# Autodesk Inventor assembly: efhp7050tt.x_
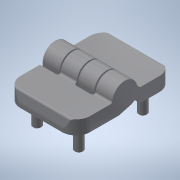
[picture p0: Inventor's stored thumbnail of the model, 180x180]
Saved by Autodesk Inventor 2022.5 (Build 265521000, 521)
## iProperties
Part Number: efhp7050tt.x_
Material: 一般
Document SubType Name: Assembly
Designer: ImaoCorp
Sending System: SOLIDWORKS 2017-2017317
MC: AMD64
MC_MODEL: Intel64 Family 6 Model 60 Stepping 3, GenuineIntel
OS: Windows_NT
FRU: Parasolid Version 29.0, build 201,  4-17-2017
FORMAT: text
GUISE: transmit
KEY: efhp7050tt
FILE: efhp7050tt.x_t
DATE: Mon May 13 14:22:51 2019
Author: ImaoCorp
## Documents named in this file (4)
- X:\14_SW2022-Inv2022\00_全2023-1023新製品(TCC)まで\e\efhp7050tt\EFHP7050TT.iam
- X:\14_SW2022-Inv2022\00_全2023-1023新製品(TCC)まで\e\efhp7050tt\efhp7050tt_01.ipt
- X:\14_SW2022-Inv2022\00_全2023-1023新製品(TCC)まで\e\efhp7050tt\efhp7050tt_02.ipt
- X:\14_SW2022-Inv2022\00_全2023-1023新製品(TCC)まで\e\efhp7050tt\efhp7050tt_03.ipt
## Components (3 placed, 3 different names)
1. efhp7050tt_01
2. efhp7050tt_02
3. efhp7050tt_03
